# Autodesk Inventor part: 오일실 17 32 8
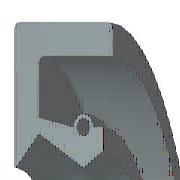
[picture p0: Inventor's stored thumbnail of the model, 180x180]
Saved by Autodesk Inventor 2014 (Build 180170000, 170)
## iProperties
IsCustomPart: 1
Created: 2012-02
Part Number: 오일실 17 32 8
Material: 고무
Description: 오일-실
Document SubType Name: Modeling
Standard: KS B 2804
Designer: mduedu
Standards Organization: KS
Language: ko-KR
Size Designation: D - 17 32 8
Categories: <MemberInstance><Categories><Category DisplayName="샤프트 부품" InternalName="7f7aeb1f-a693-4053-b835-cee3144e0d98" Mnemonic="SHFT"><Category DisplayName="실링" Intern
Density: 0.93 g/cm^3
Appearance: Rubber - Black - Version 1.1
Author: mduedu
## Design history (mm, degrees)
revolve "본체" stored, may be unused: angle "d17" = 90 deg
revolve "스프링1" stored, may be unused: angle "d18" = 90 deg
body "Solid1"
sketch "스케치1"
  geometry: L1 (0, 16)-(8, 16); L2 (8, 14.25)-(1.75, 14.25); L3 (1.75, 10.25)-(4.9, 8.5); L4 (4.9, 8.5)-(0, 8.5); L5 (0, 0)-(9.586, 0) reference; L6 (4.9, 8.5)-(6.3, 9.375); L7 (0, 18)-(0, -3) reference; L8 (-1.941, 0)-(11.507, 0) reference; L9 (4.2, 10.6)-(1.75, 11.21); L10 (1.75, 11.21)-(1.75, 14.25); L11 (0, 16)-(0, 8.588); L12 (4.9, 8.5)-(0, 8.5); L13 (1.75, 10.25)-(0.152, 8.528); L14 (8, 16)-(8, 14.25); L15 (5.6, 10.6)-(6.3, 10.6); L16 (6.3, 10.6)-(6.3, 9.375); C1 r 0.455 at (4.9, 10.6); A1 r 0.7 centre (4.9, 10.6) between (5.6, 10.6) and (4.2, 10.6); A2 r 0.088 centre (0.088, 8.588) between (0, 8.588) and (0.152, 8.528); 1 further point
  constraints: 28 end point, 5 horizontal alignment, 5 point on line, 4 point on circle, 4 vertical alignment, 3 centre point, 3 tangent, 2 collinear, 2 horizontal, 2 perpendicular, 1 coincident, 1 parallel
  dimensions: "d0" = 32 diameter of L1 L5 (= SD2); "d1" = 1.75 distance of L1.end L2.start (= SD); "d2" = 0.91 diameter of C1 (= SPDI); "d3" = 1.4 diameter of A1 (= SPDA); "d4" = 17 diameter of L3.end L5 (= NND); "d5" = 20.5 diameter of L3.start L5 (= TKDM); "d7" = 22.42 diameter of L9.end L5 (= TKDM + 0.24 x SWDT); "d8" = 1.75 distance between parallel lines of L11 L10 (= SD); "d9" = 4.9 distance from line of L11 C1.centre (= SPDST); "d10" = 21.2 diameter of C1.centre L5 (= HLDM); "d11" = 0.0875 radius of A2 (= 0.25 x LAB); "d12" = 6.3 distance between parallel lines of L11 L16 (= SDI); "d13" = 18.75 diameter of L6.end L5 (= ABDM); "d14" = 8 distance from line of L11 L1.end (= SWDT)
fillet "모깎기1" dims "d6" = 0.3 (= RR)
other parameters: "SD2" = 32 [user parameter; used in 1 equation term], "SWDT" = 8 [user parameter; used in 2 equation terms], "RR" = 0.3 [user parameter; used in 1 equation term], "SD" = 1.75 [user parameter; used in 2 equation terms], "NND" = 17 [user parameter; used in 1 equation term], "SPDA" = 1.4 [user parameter; used in 1 equation term], "SPDI" = 0.91 [user parameter; used in 1 equation term], "TKDM" = 20.5 [user parameter; used in 2 equation terms], "HLDM" = 21.2 [user parameter; used in 1 equation term], "ABDM" = 18.75 [user parameter; used in 1 equation term], "SDI" = 6.3 [user parameter; used in 1 equation term], "SPDST" = 4.9 [user parameter; used in 1 equation term], "LAB" = 0.35 [user parameter; used in 1 equation term], "d15" = 0, "d16" = 0, "d19" = 0
